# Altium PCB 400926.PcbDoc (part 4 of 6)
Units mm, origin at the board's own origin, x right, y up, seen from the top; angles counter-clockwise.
Board outline 148.5 x 63.5 mm, 4 copper layers (Top Layer, Mid-Layer 1, Mid-Layer 2, Bottom Layer), stack 1.514 mm thick; 311 components, 281 nets, 1495 pads, 2232 vias.
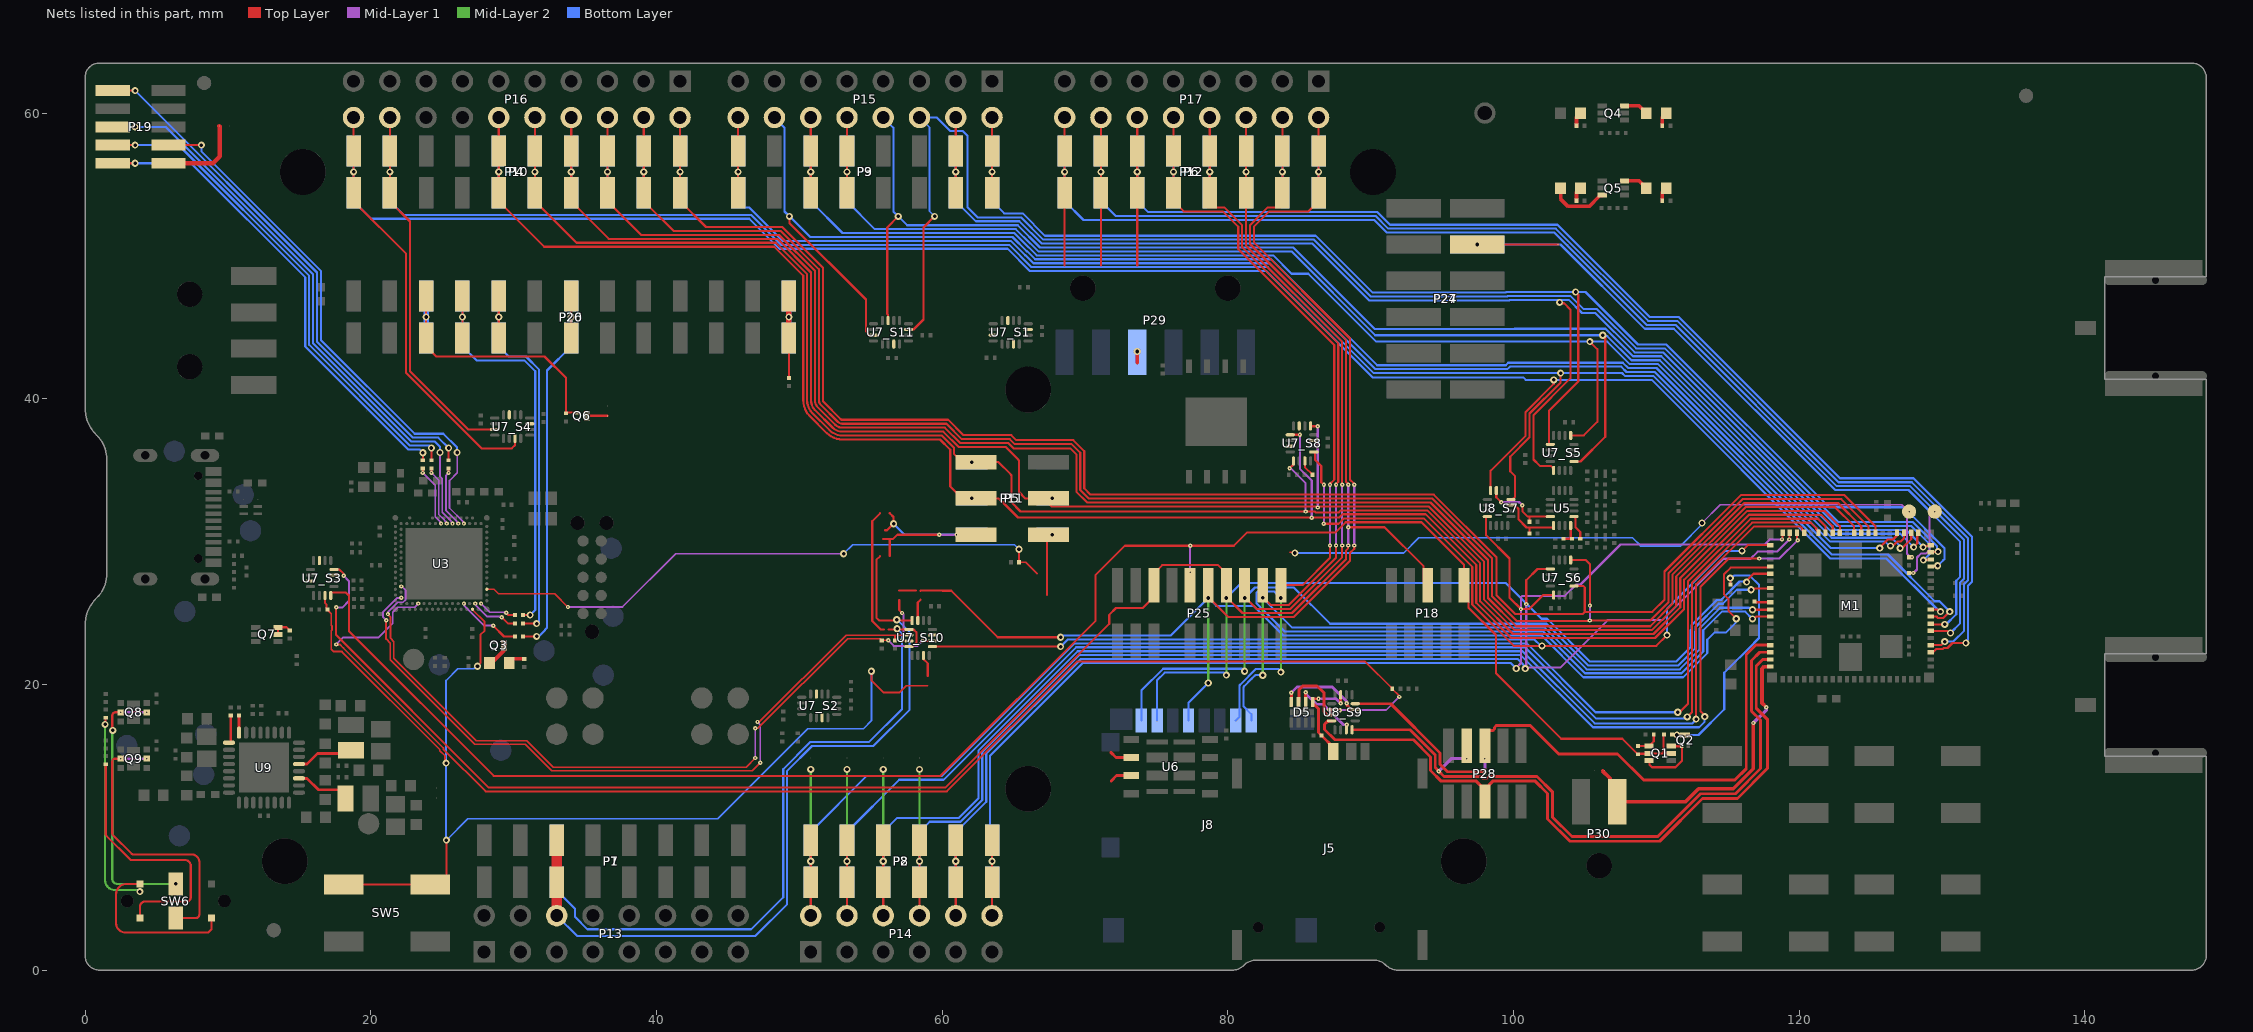
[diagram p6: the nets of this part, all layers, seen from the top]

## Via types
v1: diameter 0.5, hole 0.25, Top Layer to Bottom Layer, tented both sides, 1704 vias
v2: diameter 0.3, hole 0.1, Top Layer to Mid-Layer 1, tented top, 426 vias
v3: diameter 0.3, hole 0.1, Top Layer to Mid-Layer 1, tented both sides, 93 vias
v4: diameter 0.61, hole 0.305, Top Layer to Bottom Layer, tented both sides, 9 vias

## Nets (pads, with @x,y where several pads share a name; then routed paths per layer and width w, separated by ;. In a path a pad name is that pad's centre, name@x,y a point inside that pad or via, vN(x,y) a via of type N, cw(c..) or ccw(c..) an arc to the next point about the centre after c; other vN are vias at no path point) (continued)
NetLED1_2: LED1.2 R39.1 | length 1
  Top Layer w0.254: R39.1@104.413,59.117 104.413,59.689 LED1.2@104.698,59.974
NetLED2_1: LED2.1 Q4.3 | length 1.8
  Top Layer w0.254: Q4.3@107.75,60.499 Q4.3@107.775,60.499 108.801,60.499 109.022,60.278 109.047,60.278 109.301,60.024 LED2.1@109.301,59.999
NetLED2_2: LED2.2 R40.1 | length 1
  Top Layer w0.254: R40.1@110.413,59.117 110.413,59.689 110.698,59.974 LED2.2@110.698,59.999
NetLED3_1: LED3.1 Q5.6 | length 4.1
  Top Layer w0.254: LED3.1@103.301,54.749 103.301,53.99 103.827,53.465 105.304,53.465 Q5.6@106.039,54.201 ; Q5.6@106.202,54.201 Q5.6@106.25,54.249
NetLED3_2: LED3.2 R41.1 | length 1
  Top Layer w0.254: R41.1@104.413,53.867 104.413,54.439 104.698,54.724 LED3.2@104.698,54.749
NetLED4_1: LED4.1 Q5.3 | length 1.4
  Top Layer w0.254: Q5.3@107.75,55.249 Q5.3@107.775,55.249 108.801,55.249 LED4.1@109.022,55.028
NetLED4_2: LED4.2 R42.1 | length 1
  Top Layer w0.254: R42.1@110.413,53.867 110.413,54.439 110.698,54.724 LED4.2@110.698,54.749
NetLED5_1: LED5.1 Q3.3 | length 1.7
  Top Layer w0.25: LED5.1@28.301,21.499 28.45,21.499 29.325,22.374 Q3.3@29.325,22.724
NetLED5_2: LED5.2 R33.1 | length 1.2
  Top Layer w0.25: LED5.2@29.698,21.499 29.983,21.784 R33.1@30.75,21.784
NetM1_10: M1.10 R1.2 | length 1.1
  Top Layer w0.15: R1.2@116.885,25.799 116.935,25.749 M1.10@117.975,25.749
NetM1_99: M1.99 TP1.1 | length 5.4
  Top Layer w0.15: M1.99@127.7,27.799 v3(128,27.799)
  Mid-Layer 1 w0.15: v3(128,27.799) 128.25,28.049 128.25,28.885 128.521,29.157 128.863,29.157 129.135,29.428 129.135,31.734 v3(129.5,32.099)
NetM1_101: M1.101 SB11.2 TP2.1 | length 49.2
  Top Layer w0.125: SB11.2@84.35,29.249 84.539,29.249 84.556,29.232 84.667,29.232 v1(84.7,29.199)
  Top Layer w0.15: M1.101@127.7,28.899 127.703,28.902 127.898,28.902 v3(127.9,28.904)
  Mid-Layer 1 w0.125: v1(113.2,31.299) 114.477,32.576 127.176,32.576 127.653,32.099 v3(127.7,32.099)
  Mid-Layer 1 w0.15: v3(127.7,32.099) 127.7,32.086 127.55,31.936 127.55,29.149 127.785,28.914 127.891,28.914 v3(127.9,28.904)
  Bottom Layer w0.125: v1(84.7,29.199) 92.319,29.199 93.381,30.261 108.337,30.261 108.9,29.699 111.7,29.699 113.2,31.199 v1(113.2,31.299)
NetP5_6: P5.6 P11.6 SB18.1 SB19.2 | length 4
  Top Layer w0.152: 67.338,26.274 P5.6@67.338,30.262
  other v1: 67.722,30.48
NetP19_1: P19.1 SB15.1 SB16.1 | length 5.9
  Top Layer w0.3: P19.1@5.836,56.49 8.95,56.49 9.438,56.977 9.438,57.602 9.438,59.056 SB16.1@9.4,59.094
NetP20_3: P20.3 P26.3 Q6.1 R67.1 | length 20.9
  Top Layer w0.15: P20.3@23.876,47.752 P20.3@23.876,47.185 v1(23.876,45.72) P20.3@23.876,44.255 23.876,43.673 24.589,42.96 32.164,42.96 33.675,41.449 R67.1@33.675,39.024 ; R67.1@33.675,38.984 R67.1@33.675,39.024 ; Q6.1@34.425,39.024 R67.1@33.675,39.024
  Bottom Layer w0.381: P26.3@23.876,44.255 v1(23.876,45.72) P26.3@23.876,47.185
NetP20_13: P20.13 P26.13 R68.2 | length 9.3
  Top Layer w0.152: R68.2@49.276,41.459 P20.13@49.276,44.255 49.276,44.203 P20.13@49.71,43.769
  Top Layer w0.381: P20.13@49.276,44.255 v1(49.276,45.72) P20.13@49.276,47.185
  Bottom Layer w0.381: P26.13@49.276,44.255 v1(49.276,45.72) P26.13@49.276,47.185
NetP29_3: P29.3 SB20.2 | length 0.8
  Top Layer w0.254: 73.66,42.516 SB20.2@73.66,42.554 v1(73.66,43.309)
NetQ1_3: Q1.3 Q1.6 Q2.1 | length 4.7
  Top Layer w0.15: Q1.6@109.49,14.674 109.537,14.627 109.537,14.362 109.7,14.199 111.348,14.199 111.79,14.641 Q2.1@111.79,15.724 ; Q1.3@111.04,15.674 111.74,15.674 Q2.1@111.79,15.724 ; Q2.1@111.79,15.749 Q2.1@111.79,15.724
NetQ1_4: Q1.4 R8.2 R10.2 | length 1.7
  Top Layer w0.15: R10.2@108.715,15.684 109.5,15.684 109.825,16.009 R8.2@109.825,16.499
NetQ6_3: Q6.3 SB17.1 | length 1.5
  Top Layer w0.15: Q6.3@35.125,38.799 35.135,38.809 SB17.1@36.576,38.809
NetQ7_5: Q7.5 Q7.6 R75.2 | length 1.4
  Top Layer w0.15: Q7.5@13.5,23.499 Q7.6@13.5,23.999 14.11,23.999 R75.2@14.325,23.784
NetQ8_2: Q8.2 Q8.5 SW6.5 | length 18.6
  Top Layer w0.15: v1(1.936,16.777) 1.9,16.813 1.9,17.799 cw(c2.15,17.799) 2.15,18.049 v2(2.495,18.049)
  Mid-Layer 1 w0.15: v2(2.495,18.049) v2(4.305,18.049)
  Mid-Layer 2 w0.15: v1(1.936,16.777) 1.9,16.741 1.9,6.388 ccw(c2.254,6.388) 2.254,6.034 v1(6.35,6.034)
NetQ9_2: Q9.2 Q9.5 SW6.2 | length 20.1
  Top Layer w0.15: v2(2.495,14.799) 2.1,14.799 ccw(c2.1,14.599) 1.9,14.599 1.9,9.561 ccw(c2.05,9.561) 1.944,9.455 3.256,8.143 ccw(c3.362,8.249) 3.362,8.099 7.46,8.099 cw(c7.46,7.559) 8,7.559 8,3.899 cw(c7.735,3.899) 7.735,3.634 SW6.2@6.35,3.634
  Mid-Layer 1 w0.15: v2(2.495,14.799) v2(4.305,14.799)
NetR36_1: R36.1 U9.17 | length 2
  Top Layer w0.2: U9.17@10.075,15.924 ccw(c10.075,16.049) 10.2,16.049 R36.1@10.2,17.814
NetR37_1: R37.1 U9.16 | length 1.2
  Top Layer w0.2: R37.1@10.769,17.821 10.769,16.624 U9.16@10.775,16.624
NetR51_1: R51.1 U5.1 | length 1.7
  Top Layer w0.15: U5.1@104.235,31.749 104.34,31.644 104.34,31.013 104.68,30.673 R51.1@104.68,30.196
NetR58_1: R58.1 R59.2 U5.16 | length 1.5
  Top Layer w0.15: R59.2@103.511,30.196 R58.1@104.095,30.196 104.01,30.281 U5.16@104.01,31.124
NetR77_2: R77.2 SW6.3 SW6.4 | length 26.3
  Top Layer w0.15: v1(1.4,17.199) 1.425,17.224 1.425,17.639 R77.2@1.45,17.664 ; SW6.4@3.85,6.034 2.901,6.034 ccw(c2.901,5.308) 2.175,5.308 2.175,3.278 ccw(c2.819,3.278) 2.819,2.634 8.573,2.634 ccw(c8.573,2.784) 8.679,2.678 8.806,2.805 ccw(c8.7,2.911) 8.85,2.911 SW6.3@8.85,3.634
  Mid-Layer 2 w0.15: v1(1.4,17.199) 1.4,6.299 ccw(c2.1,6.299) 2.1,5.599 3.735,5.599 cw(c3.735,5.494) v1(3.84,5.494)
NetR79_1: R79.1 SW6.1 | length 18.8
  Top Layer w0.15: R79.1@1.45,14.414 1.45,9.511 ccw(c1.6,9.511) 1.494,9.405 3.156,7.743 ccw(c3.262,7.849) 3.262,7.699 7.011,7.699 cw(c7.011,7.31) 7.4,7.31 7.4,5.099 cw(c7.1,5.099) 7.1,4.799 4.2,4.799 ccw(c4.2,4.449) 3.85,4.449 SW6.1@3.85,3.634
NetSB13_1: SB13.1 U6.2 | length 1.6
  Top Layer w0.2: 71.812,15.249 72.177,14.884 U6.2@73.25,14.884
NetSB14_1: SB14.1 U6.3 | length 1.6
  Top Layer w0.2: SB14.1@71.838,13.249 72.203,13.614 U6.3@73.25,13.614
NO.CH1_S1: U7_S1.15
NO.CH1_S8: R35.1 U7_S8.15 | length 1.2
  Top Layer w0.125: U7_S8.15@85.4,35.649 85.4,35.208 R35.1@85.938,34.67
NO.CH1_S9: C48.1 D5.5 J5.C1 U8_S9.15 | length 6.8
  Top Layer w0.2: D5.5@85.95,18.774 85.95,18.699 86.35,18.299 86.35,16.634 C48.1@86.56,16.424 87.38,15.604 J5.C1@87.38,15.299 ; D5.5@85.95,18.999 v2(86.35,18.999) ; v2(87.9,18.674) U8_S9.15@87.9,19.274
  Mid-Layer 1 w0.2: v2(86.35,18.999) 87.575,18.999 v2(87.9,18.674)
NO.CH1_S10: SB22.2 U7_S10.15 | length 1.5
  Top Layer w0.15: U7_S10.15@58.3,24.474 58.3,25.737 58.5,25.937
NO.CH2_S1: U7_S1.3
NO.CH2_S2: U7_S2.3
NO.CH2_S3: U7_S3.3
NO.CH2_S8: U7_S8.3
NO.CH2_S9: D5.7 U8_S9.3 | length 4.9
  Top Layer w0.2: D5.7@84.95,18.774 84.975,18.799 84.975,19.624 85.25,19.899 86.255,19.899 86.725,19.429 86.725,18.11 86.986,17.849 U8_S9.3@87.275,17.849
NO.CH2_S10: SB23.2 U7_S10.3 | length 3.6
  Top Layer w0.15: SB23.2@57,25.911 SB23.2@57,25.899 57,25.199 v2(57.2,24.999) ; v2(57.15,23.049) U7_S10.3@57.675,23.049
  Mid-Layer 1 w0.15: v2(57.15,23.049) 57.3,23.199 57.3,24.899 v2(57.2,24.999)
NO.CH3_S1: U7_S1.7
NO.CH3_S3: U7_S3.7
NO.CH3_S4: U7_S4.7
NO.CH3_S8: U7_S8.7
NO.CH3_S9: D5.6 U8_S9.7 | length 4.9
  Top Layer w0.2: D5.6@85.45,18.774 v2(85.45,19.449) ; U8_S9.7@88.3,16.824 88.3,17.149 v2(88.325,17.174)
  Mid-Layer 1 w0.2: v2(85.45,19.449) 85.45,19.369 86.204,18.615 86.659,18.615 88.1,17.174 v2(88.325,17.174)
NO.CH3_S10: SB24.1 U7_S10.7 | length 1.6
  Top Layer w0.15: U7_S10.7@58.7,22.024 58.7,21.771 59,21.471 SB24.1@59,20.599 SB24.1@59,20.587
NO.CH4_S1: U7_S1.11
NO.CH4_S2: U7_S2.11
NO.CH4_S3: U7_S3.11
NO.CH4_S4: U7_S4.11
NO.CH4_S8: U7_S8.11
NO.CH4_S9: D5.8 U8_S9.11 | length 6.1
  Top Layer w0.2: D5.8@84.45,18.774 v2(84.45,19.424) ; v2(88.325,18.674) 88.325,18.549 88.625,18.249 U8_S9.11@88.925,18.249
  Mid-Layer 1 w0.2: v2(84.45,19.424) 84.85,19.824 87.315,19.824 88.325,18.814 v2(88.325,18.674)
NO.CH4_S10: U7_S10.11
NO.CH4_S11: U7_S11.11
nRESET: Q2.3 R2.1 R9.2 | length 17.6
  Top Layer w0.15: R9.2@111.1,16.499 v1@111.398,16.499 ; v1(111.44,16.458) v1@111.398,16.499 ; Q2.3@112.015,16.449 111.965,16.499 v1@111.398,16.499 ; v1(115.181,27.437) 115.191,27.428 115.191,26.993 R2.1@115.2,26.984
  Bottom Layer w0.15: v1(111.44,16.458) 112.959,16.458 114.762,18.261 114.762,20.811 116.837,22.886 116.837,22.904 117.187,23.254 117.187,26.972 116.548,27.612 115.444,27.612 115.269,27.437 v1(115.181,27.437)
P0.00: M1.56 P3.1 P9.1 P15.2 U7_S5.1 | length 99.1
  Top Layer w0.15: P3.1@63.5,54.415 v1(63.5,55.88) P3.1@63.5,57.345 P15.2@63.5,59.69 ; U7_S5.1@102.585,36.808 102.5,36.893 102.5,39.171 104.535,41.206 104.535,47.289 v1(104.35,47.474) ; M1.56@129.225,28.249 129.375,28.274 129.604,28.274 ccw(c129.603,28.424) v1(129.694,28.305)
  Bottom Layer w0.15: P9.1@63.5,57.345 v1(63.5,55.88) P9.1@63.5,54.415 63.5,53.83 64.356,52.974 65.639,52.974 67.198,51.415 86.148,51.415 90.138,47.425 99.46,47.425 99.509,47.474 v1(104.35,47.474) 105.041,47.474 108.715,43.799 110.7,43.799 122.1,32.399 127.314,32.399 130.175,29.538 130.175,28.774 130.089,28.688 129.734,28.333 cw(c129.628,28.439) v1(129.694,28.305)
P0.01: M1.57 P3.2 P9.2 P15.4 U7_S5.5 | length 103.3
  Top Layer w0.15: P3.2@60.96,54.415 v1(60.96,55.88) P3.2@60.96,57.345 P15.4@60.96,59.69 ; U7_S5.5@102.81,34.983 102.81,35.098 102.61,35.298 101.851,35.298 101.4,35.749 101.4,38.849 103.985,41.434 103.985,46.248 103.545,46.688 103.296,46.688 v1(103.235,46.749) ; v1(128.7,28.699) 128.725,28.724 129.2,28.724 M1.57@129.225,28.749
  Bottom Layer w0.15: P9.2@60.96,57.345 v1(60.96,55.88) P9.2@60.96,54.415 60.96,53.83 62.366,52.424 65.411,52.424 66.97,50.865 85.92,50.865 89.91,46.875 99.688,46.875 99.737,46.924 v1@103.235,46.924 ; v1(103.235,46.749) v1@103.235,46.924 ; v1(128.7,28.699) 129.135,29.134 129.135,29.801 127.842,31.093 122.628,31.093 110.472,43.249 108.488,43.249 105.738,45.999 104.799,45.999 103.874,46.924 v1@103.235,46.924
P0.02: M1.58 P15.6 U7_S11.15 | length 103.8
  Top Layer w0.15: U7_S11.15@57.643,44.849 58,44.849 58.695,45.544 58.695,51.991 v1(59.473,52.769) ; M1.58@129.225,29.249 129.25,29.274 129.7,29.274 v1(129.725,29.299)
  Bottom Layer w0.125: P15.6@58.42,59.69 58.518,59.592 59.117,58.992 59.117,53.125 v1(59.473,52.769)
  Bottom Layer w0.15: P15.6@58.518,59.592 58.616,59.69 59.616,59.69 60.566,58.74 61.453,58.74 61.78,58.413 61.78,53.399 62.48,52.699 65.525,52.699 67.084,51.14 86.034,51.14 90.024,47.15 99.574,47.15 99.623,47.199 103.988,47.199 104.913,46.274 105.852,46.274 108.602,43.524 110.586,43.524 122.742,31.368 127.956,31.368 129.658,29.666 129.658,29.366 v1(129.725,29.299)
P0.03: M1.59 P15.8 U7_S11.3 | length 97
  Top Layer w0.15: U7_S11.3@56.218,45.474 56.218,45.874 56.155,45.936 56.155,46.05 56.155,51.991 v1(56.933,52.769) ; v1(128.685,29.614) 128.752,29.681 129.157,29.681 M1.59@129.225,29.749
  Bottom Layer w0.15: P15.8@55.88,59.69 56.59,58.98 56.59,53.113 v1(56.933,52.769) 57.554,52.149 65.297,52.149 66.856,50.59 84.573,50.59 90.278,44.885 100.072,44.885 100.086,44.899 106.449,44.899 108.374,42.974 110.358,42.974 122.514,30.818 127.481,30.818 v1(128.685,29.614)
P0.04: M1.61 P3.5 P9.5 P15.10 U7_S5.9 | length 104.7
  Top Layer w0.15: P3.5@53.34,54.415 P3.5@53.34,57.345 P15.10@53.34,59.69 ; U7_S5.9@104.235,35.608 104.693,35.608 106.429,37.343 106.429,44.273 v1(106.252,44.449) ; v1(128.015,29.614) 128.015,29.617 128.275,29.877 128.275,30.549 M1.61@128.35,30.624
  Bottom Layer w0.15: P9.5@53.34,57.345 v1(53.34,55.88) P9.5@53.34,54.415 53.34,53.83 55.296,51.874 65.158,51.874 66.158,50.874 66.183,50.874 66.742,50.315 84.459,50.315 90.325,44.449 v1(106.252,44.449) 106.319,44.382 106.577,44.382 108.26,42.699 110.245,42.699 122.4,30.543 127.086,30.543 v1(128.015,29.614)
P0.05: M1.62 P3.6 P9.6 P15.12 U7_S5.13 | length 104.8
  Top Layer w0.15: P3.6@50.8,54.415 P3.6@50.8,57.345 P15.12@50.8,59.69 ; U7_S5.13@104.01,37.433 104.92,37.433 105.879,38.391 105.879,43.47 v1(105.35,43.999) ; v1(127.071,29.535) 127.138,29.602 127.278,29.602 127.85,30.174 M1.62@127.85,30.624
  Bottom Layer w0.15: P9.6@50.8,57.345 v1(50.8,55.88) P9.6@50.8,54.415 50.8,53.83 53.031,51.599 65.044,51.599 66.044,50.599 66.069,50.599 66.628,50.04 83.173,50.04 84.464,48.749 85.636,48.749 90.37,44.015 105.334,44.015 v1(105.35,43.999) 106.571,43.999 108.146,42.424 110.131,42.424 122.286,30.268 126.467,30.268 127.004,29.731 127.004,29.602 v1(127.071,29.535)
P0.06: M1.63 P15.14 U7_S11.7 | length 106.6
  Top Layer w0.15: v1(49.313,52.769) 49.313,52.297 54.668,46.942 54.668,44.721 54.94,44.449 U7_S11.7@55.193,44.449 ; v1(126.4,29.699) 126.519,29.699 126.572,29.752 126.606,29.752 126.862,30.007 127.108,30.007 127.35,30.249 M1.63@127.35,30.624
  Bottom Layer w0.15: P15.14@48.26,59.69 48.97,58.98 48.97,53.113 v1(49.313,52.769) 50.759,51.324 64.93,51.324 65.93,50.324 65.955,50.324 66.514,49.765 83.034,49.765 90.454,42.345 99.46,42.345 99.639,42.524 107.657,42.524 108.032,42.149 110.017,42.149 122.172,29.993 126.023,29.993 126.317,29.699 v1(126.4,29.699)
P0.07: M1.64 P3.8 P9.8 P15.16 | length 100.7
  Top Layer w0.15: P3.8@45.72,54.415 P3.8@45.72,57.345 P15.16@45.72,59.69 ; v1(125.648,29.543) 125.648,29.583 126.214,30.149 126.573,30.149 126.85,30.426 M1.64@126.85,30.624
  Bottom Layer w0.15: P9.8@45.72,57.345 v1(45.72,55.88) P9.8@45.72,54.415 45.72,53.83 46.155,53.395 46.486,53.395 48.832,51.049 64.817,51.049 65.817,50.049 65.841,50.049 66.4,49.49 82.92,49.49 90.34,42.07 99.574,42.07 99.753,42.249 107.543,42.249 107.918,41.874 109.903,41.874 122.233,29.543 v1(125.648,29.543)
P0.08: M1.67 P4.1 P10.1 P16.2 U7_S6.1 | length 121.5
  Top Layer w0.15: P16.2@41.656,59.69 P4.1@41.656,57.345 v1(41.656,55.88) P4.1@41.656,54.415 41.656,53.83 43.468,52.018 48.814,52.018 51.65,49.182 51.65,39.886 ccw(c51.8,39.886) 51.694,39.78 52.906,38.568 ccw(c53.012,38.674) 53.012,38.524 60.425,38.524 61.5,37.449 64.85,37.449 65.2,37.099 69.181,37.099 69.95,36.33 69.95,33.724 70.389,33.285 94.423,33.285 98.825,28.883 98.825,26.224 100.125,24.924 104.851,24.924 105.005,25.078 ; U7_S6.1@104.235,26.883 104.909,26.883 104.997,26.795 104.997,25.087 105.005,25.078 ; M1.67@125.35,30.624 125.35,31.074 123.175,33.249 115.92,33.249 110.575,27.904 110.575,25.929 109.724,25.078 105.005,25.078
  Bottom Layer w0.15: P10.1@41.656,54.415 v1(41.656,55.88) P10.1@41.656,57.345
P0.09: M1.68 P4.2 P10.2 P16.4 U7_S6.5 | length 126.6
  Top Layer w0.15: P16.4@39.116,59.69 P4.2@39.116,57.345 v1(39.116,55.88) P4.2@39.116,54.415 39.116,53.83 41.203,51.743 48.7,51.743 51.375,49.069 51.375,39.886 ccw(c51.8,39.886) 51.498,39.587 52.713,38.372 ccw(c53.012,38.674) 53.012,38.249 60.311,38.249 61.386,37.174 64.736,37.174 65.086,36.824 69.067,36.824 69.675,36.216 69.675,33.61 70.275,33.01 94.309,33.01 98.495,28.824 98.495,26.165 100.211,24.449 105.287,24.449 105.312,24.474 v2(105.35,24.474) 109.584,24.474 110.85,25.74 110.85,27.79 116.034,32.974 122.95,32.974 124.85,31.074 M1.68@124.85,30.624 ; U7_S6.5@104.01,28.708 105.066,28.708 105.354,28.42 v2(105.354,25.52)
  Mid-Layer 1 w0.15: v2(105.35,24.474) 105.352,24.476 105.352,25.517 v2(105.354,25.52)
  Bottom Layer w0.15: P10.2@39.116,54.415 v1(39.116,55.88) P10.2@39.116,57.345
P0.10: M1.69 P4.3 P10.3 P16.6 | length 123.3
  Top Layer w0.15: P16.6@36.576,59.69 P4.3@36.576,57.345 v1(36.576,55.88) P4.3@36.576,54.415 36.576,53.83 38.938,51.468 48.586,51.468 51.1,48.955 51.1,39.886 ccw(c51.8,39.886) 51.302,39.394 52.52,38.177 ccw(c53.012,38.674) 53.012,37.974 60.197,37.974 61.272,36.899 64.622,36.899 64.997,36.524 68.978,36.524 69.4,36.102 69.4,33.496 70.161,32.735 94.196,32.735 98.22,28.711 98.22,26.051 100.197,24.074 109.573,24.074 111.125,25.626 111.125,27.676 116.148,32.699 122.725,32.699 124.35,31.074 M1.69@124.35,30.624
  Bottom Layer w0.15: P10.3@36.576,54.415 v1(36.576,55.88) P10.3@36.576,57.345
P0.11: M1.70 P4.4 P5.4 P10.4 P11.4 P16.8 U7_S8.5 | length 131.5
  Top Layer w0.15: P16.8@34.036,59.69 P4.4@34.036,57.345 v1(34.036,55.88) P4.4@34.036,54.415 34.036,53.823 36.665,51.193 39.881,51.193 39.882,51.192 40.483,51.192 40.485,51.193 48.473,51.193 50.825,48.841 50.825,39.886 ccw(c51.8,39.886) 51.108,39.199 52.325,37.982 ccw(c53.012,38.674) 53.012,37.699 60.083,37.699 61.158,36.624 64.45,36.624 65.331,35.743 cw(c65.225,35.637) 65.375,35.637 65.375,33.536 ccw(c65.525,33.536) 65.418,33.431 ; 65.419,33.43 65.829,33.02 P5.4@67.119,33.02 ; P5.4@67.437,33.02 P5.4@67.119,33.02 ; U7_S8.5@85.8,38.099 85.825,38.074 v2(86.3,38.074) ; v2(86.3,32.385) 86.269,32.416 ccw(c86.163,32.31) 86.163,32.46 67.679,32.46 P5.4@67.119,33.02 ; v2@86.416,32.46 94.082,32.46 97.945,28.597 97.945,25.937 100.083,23.799 109.687,23.799 111.4,25.512 111.4,27.562 116.262,32.424 122.5,32.424 123.85,31.074 M1.70@123.85,30.624
  Mid-Layer 1 w0.15: v2(86.3,32.385) v2(86.3,38.074)
  Bottom Layer w0.15: P10.4@34.036,54.415 v1(34.036,55.88) P10.4@34.036,57.345
  other v1: 67.722,33.02
P0.12: M1.72 P4.5 P5.1 P10.5 P11.1 P16.10 U7_S8.13 | length 130.9
  Top Layer w0.15: P16.10@31.496,59.69 P4.5@31.496,57.345 v1(31.496,55.88) P4.5@31.496,54.415 31.496,53.83 34.408,50.918 39.767,50.918 39.769,50.917 40.597,50.917 40.599,50.918 48.359,50.918 50.55,48.727 50.55,39.886 ccw(c51.8,39.886) 50.914,39.005 52.13,37.788 ccw(c53.012,38.674) 53.012,37.424 59.969,37.424 60.844,36.549 60.844,36.12 61.404,35.56 v1(62.072,35.56) P5.1@62.357,35.56 63.944,35.56 64.803,34.702 cw(c64.697,34.596) 64.847,34.596 64.847,33.671 64.847,32.814 ccw(c64.997,32.814) 64.89,32.709 65.456,32.143 ccw(c65.562,32.249) 65.562,32.099 v2(85.45,32.099) ; v2(84.325,35.124) 84.6,35.399 U7_S8.13@84.6,35.649 ; v2@85.47,32.079 85.491,32.099 86.091,32.099 86.155,32.035 87.761,32.035 87.911,32.185 93.968,32.185 97.67,28.483 97.67,25.823 99.969,23.524 109.801,23.524 111.675,25.398 111.675,27.448 116.376,32.149 119.538,32.149 120.538,32.149 120.541,32.147 121.777,32.147 122.85,31.074 M1.72@122.85,30.624
  Mid-Layer 1 w0.15: v2(84.325,35.124) 84.411,35.124 85.45,34.085 v2(85.45,32.099)
  Bottom Layer w0.15: P10.5@31.496,54.415 v1(31.496,55.88) P10.5@31.496,57.345
P0.13/AIN0: M1.73 P4.6 P5.3 P10.6 P11.3 P16.12 U7_S8.9 | length 135.8
  Top Layer w0.15: P16.12@28.956,59.69 P4.6@28.956,57.345 v1(28.956,55.88) P4.6@28.956,54.415 28.956,53.83 32.143,50.643 39.653,50.643 39.655,50.642 40.711,50.642 40.713,50.643 48.245,50.643 50.275,48.613 50.275,39.886 ccw(c51.8,39.886) 50.72,38.81 51.936,37.594 ccw(c53.012,38.674) 53.012,37.149 59.855,37.149 60.569,36.435 60.569,33.855 61.404,33.02 P5.3@62.357,33.02 63.917,33.02 cw(c63.917,32.87) 64.023,32.976 65.281,31.718 ccw(c65.387,31.824) 65.387,31.674 v2(85.875,31.674) ; U7_S8.9@84.375,37.474 v2(85.05,37.474) ; v2@85.944,31.674 87.789,31.674 88.025,31.91 93.854,31.91 97.395,28.369 97.395,25.709 99.855,23.249 109.915,23.249 111.95,25.284 111.95,27.334 116.49,31.874 119.425,31.874 120.425,31.874 120.427,31.872 121.552,31.872 122.35,31.074 M1.73@122.35,30.624
  Mid-Layer 1 w0.15: v2(85.05,37.474) 85.05,35.099 85.875,34.274 v2(85.875,31.674)
  Bottom Layer w0.15: P10.6@28.956,54.415 v1(28.956,55.88) P10.6@28.956,57.345
  other v1: 62.072,33.02
P0.14/AIN1: M1.74 P2.1 P8.1 P14.2 SB5.1 | length 105
  Top Layer w0.15: P14.2@50.8,3.81 P2.1@50.8,6.155 v1(50.8,7.62) P2.1@50.8,9.085 ; v1(111.5,18.054) 111.567,18.121 111.692,18.121 112.225,18.654 112.225,27.22 116.604,31.599 119.311,31.599 120.311,31.599 120.313,31.597 121.327,31.597 121.85,31.074 M1.74@121.85,30.624
  Mid-Layer 2 w0.15: v1(50.8,7.62) v1(50.8,14.049)
  Bottom Layer w0.15: P8.1@50.8,6.155 v1(50.8,7.62) P8.1@50.8,9.085 50.8,9.67 54.729,13.599 59.994,13.599 69.269,22.874 100.925,22.874 105.745,18.054 v1(111.5,18.054)
P0.15/AIN2: M1.75 P2.2 P8.2 P14.4 SB6.1 | length 102
  Top Layer w0.15: P14.4@53.34,3.81 P2.2@53.34,9.085 ; v1@112.165,17.725 112.5,18.06 112.5,27.106 116.718,31.324 119.197,31.324 120.197,31.324 120.199,31.322 120.81,31.322 121.2,30.932 121.2,30.849 121.35,30.699 M1.75@121.35,30.624
  Mid-Layer 2 w0.15: v1(53.34,7.62) v1(53.34,14.049)
  Bottom Layer w0.15: P8.2@53.34,6.155 v1(53.34,7.62) P8.2@53.34,9.085 53.34,9.67 56.994,13.324 60.108,13.324 69.383,22.599 100.811,22.599 105.806,17.604 111.95,17.604 112.07,17.724 v1(112.165,17.724)
P0.16/AIN3: M1.77 P2.3 P8.3 P14.6 SB9.1 | length 100.5
  Top Layer w0.15: P14.6@55.88,3.81 P2.3@55.88,6.155 v1(55.88,7.62) P2.3@55.88,9.085 ; v1(112.792,17.568) 112.792,27.009 116.832,31.049 119.083,31.049 120.083,31.049 120.2,30.932 120.2,30.849 120.35,30.699 M1.77@120.35,30.624
  Mid-Layer 2 w0.15: v1(55.88,7.62) v1(55.88,14.049)
  Bottom Layer w0.15: P8.3@55.88,6.155 v1(55.88,7.62) P8.3@55.88,9.085 55.88,9.67 56.865,10.655 61.178,10.655 62.539,12.016 62.539,15.366 69.497,22.324 100.632,22.324 105.682,17.274 112.538,17.274 112.792,17.528 v1(112.792,17.568)
P0.17/AIN4: M1.78 P2.4 P8.4 P14.8 SB10.1 | length 97.8
  Top Layer w0.15: P14.8@58.42,3.81 P2.4@58.42,6.155 v1(58.42,7.62) P2.4@58.42,9.085 ; v1(113.39,17.747) 113.39,17.838 113.1,18.128 113.1,26.839 115.072,28.812 v3(117.2,28.812) ; M1.78@119.85,30.624 119.85,30.19 119.9,30.14 v3(119.9,30.099)
  Mid-Layer 1 w0.15: v3(117.2,28.812) 118.613,28.812 v3(119.9,30.099)
  Mid-Layer 2 w0.15: v1(58.42,7.62) v1(58.42,14.049)
  Bottom Layer w0.15: P8.4@58.42,6.155 v1(58.42,7.62) P8.4@58.42,9.085 58.42,9.67 59.13,10.38 61.292,10.38 62.814,11.902 62.814,15.252 69.611,22.049 100.518,22.049 105.568,16.999 113,16.999 113.383,17.382 113.383,17.74 v1(113.39,17.747)
P0.18/AIN5: M1.79 P2.5 P8.5 P14.10 U7_S6.9 | length 86.8
  Top Layer w0.15: P14.10@60.96,3.81 P2.5@60.96,6.155 v1(60.96,7.62) P2.5@60.96,9.085 ; v2(100.9,25.624) 100.9,27.299 101.684,28.083 U7_S6.9@102.585,28.083 ; v3(119.3,30.149) 119.325,30.174 119.325,30.599 M1.79@119.35,30.624
  Mid-Layer 1 w0.15: v1(100.828,21.102) v1@100.9,21.174 ; v2(100.9,25.624) v1@100.9,21.174 ; v3(119.3,30.149) 118.45,29.299 117.1,29.299 116.6,28.799 114.711,28.799 110.411,24.499 106.6,24.499 103.275,21.174 v1@100.9,21.174
  Bottom Layer w0.15: P8.5@60.96,6.155 v1(60.96,7.62) P8.5@60.96,9.085 60.96,9.67 61.395,10.105 61.406,10.105 63.089,11.788 63.089,15.138 69.725,21.774 100.3,21.774 100.714,21.36 100.714,21.311 100.828,21.197 v1(100.828,21.102)
P0.19/AIN6: M1.80 P2.6 P8.6 P14.12 U7_S6.13 U8_S7.12 | length 89.7
  Top Layer w0.15: P14.12@63.5,3.81 P2.6@63.5,6.155 v1(63.5,7.62) P2.6@63.5,9.085 ; U8_S7.12@98.175,31.749 98.122,31.749 98.09,31.717 98.09,30.445 99.725,28.81 99.725,26.074 v2(100.525,25.274) 101.114,25.274 102.098,26.258 U7_S6.13@102.81,26.258 ; v3(118.8,30.149) 118.825,30.174 118.825,30.599 M1.80@118.85,30.624
  Mid-Layer 1 w0.15: v1(100.2,21.111) 100.2,21.174 100.525,21.499 v2(100.525,25.274) 100.525,26.111 100.613,26.199 103.6,26.199 104.4,26.999 104.7,26.999 107.5,29.799 117.6,29.799 117.95,30.149 v3(118.8,30.149)
  Bottom Layer w0.15: P8.6@63.5,6.155 v1(63.5,7.62) P8.6@63.5,9.085 63.364,9.221 63.364,15.024 69.839,21.499 99.812,21.499 v1(100.2,21.111)
P0.20/AIN7: M1.2 U7_S8.1 U7_S10.9 | length 89
  Top Layer w0.15: U7_S10.9@59.325,22.649 v1(68.3,22.649) ; U7_S8.1@86.025,36.274 86.11,36.189 86.11,35.728 86.548,35.29 86.548,34.154 v2(86.734,33.968) ; v2(86.725,31.249) 87.761,31.249 88.136,31.624 93.728,31.624 97.12,28.232 97.12,25.596 100.017,22.699 v1(102,22.699) 110.003,22.699 v1(110.751,23.448) ; v1(116,29.349) 116.4,29.749 M1.2@117.975,29.749
  Mid-Layer 1 w0.15: v2(86.725,31.249) 86.729,31.253 86.729,33.964 v2@86.725,33.968
  Bottom Layer w0.15: v1(68.3,22.649) 68.8,23.149 101.455,23.149 101.905,22.699 v1(102,22.699) ; v1(110.751,23.448) 110.751,25.293 114.808,29.349 v1(116,29.349)
P0.21: J8.5 M1.5 P6.1 P12.1 P17.2 P25.12 SB22.1 SB23.1 | length 134.2
  Top Layer w0.15: SB23.1@57,26.587 58.168,26.587 ; 58.5,26.561 58.5,26.574 60.018,26.574 60.031,26.561 60.638,26.561 63.9,23.299 v1(68.292,23.299) ; P25.12@78.667,26.081 80.025,24.724 84.625,24.724 88.559,28.658 88.559,29.208 88.853,29.502 88.853,29.721 v2(88.859,29.727) ; P17.2@86.36,59.69 P6.1@86.36,57.345 P6.1@86.36,54.415 86.36,53.83 85.65,53.12 82.914,53.12 81.83,52.036 81.83,50.944 88.559,44.215 88.559,34.338 88.859,34.038 v2(88.859,33.968) ; v1@115.505,24.599 v1(115.6,24.599) 115.05,25.149 115.05,25.996 114.731,26.315 114.731,27.693 115.213,28.174 117.9,28.174 M1.5@117.975,28.249
  Mid-Layer 1 w0.15: v2(88.859,29.727) v2(88.859,33.968)
  Mid-Layer 2 w0.15: v1(78.635,20.099) v1(78.635,26.049)
  Bottom Layer w0.15: v1(68.292,23.299) 68.387,23.299 68.512,23.424 76.01,23.424 v1(78.635,26.049) 79.185,25.499 81.8,25.499 83.875,23.424 101.975,23.424 104.897,20.502 111.881,20.502 113.566,22.187 113.566,23.126 114.082,23.642 114.893,23.642 115.539,24.288 115.539,24.538 v1(115.6,24.599) ; J8.5@77.25,17.469 77.25,18.714 v1(78.635,20.099) ; P12.1@86.36,54.415 P12.1@86.36,57.345
  other v1: 86.36,55.88
P0.22: J8.7 M1.6 P6.2 P12.2 P17.4 P18.6 P25.6 P25.14 U7_S3.4 | length 195.1
  Top Layer w0.15: U7_S3.4@17.425,28.049 17.8,28.049 18.1,27.749 v2(18.1,27.599) ; v2(17.575,25.399) 17.575,23.462 28.263,12.774 60.228,12.774 71.7,24.246 71.7,24.869 72.178,25.346 74.042,25.346 74.825,26.129 P25.6@74.825,26.949 74.825,27.769 75.405,28.349 79.325,28.349 79.905,27.769 P25.14@79.905,26.949 79.905,26.129 81.035,24.999 84.5,24.999 88.284,28.783 88.284,29.383 88.405,29.504 88.405,29.698 v2(88.434,29.727) ; P6.2@83.675,53.395 82.8,53.395 81.555,52.15 81.555,50.83 88.284,44.102 88.284,34.188 88.434,34.038 v2(88.434,33.968) ; P6.2@83.82,54.661 v1(83.82,55.88) P6.2@83.82,57.345 P17.4@83.82,59.69 ; v2(88.425,30.999) 90.975,30.999 93.713,28.261 93.713,27.236 P18.6@94,26.949 ; v1(116.322,27.162) 116.322,27.257 116.455,27.39 116.455,27.402 116.803,27.749 M1.6@117.975,27.749
  Mid-Layer 1 w0.15: v2(17.575,25.399) 17.6,25.374 17.995,25.374 18.475,25.854 18.475,27.224 v2(18.1,27.599) ; v2(88.434,29.727) v2(88.434,33.968)
  Mid-Layer 2 w0.15: v1(79.905,20.649) v1(79.905,26.049)
  Bottom Layer w0.15: J8.7@75.05,17.469 75.05,20.288 75.586,20.824 79.73,20.824 v1(79.905,20.649) ; v1(79.905,26.049) 80.955,27.099 99.463,27.099 101.963,24.599 102.356,24.599 105.353,21.602 111.403,21.602 112.4,22.599 112.4,23.773 112.466,23.839 112.466,24.131 114.252,25.918 114.545,25.918 115.827,27.2 116.285,27.2 v1(116.322,27.162) ; P12.2@83.82,54.415 P12.2@83.82,57.345
P0.23: J8.8 M1.8 P6.3 P12.3 P17.6 P25.16 | length 103.7
  Top Layer w0.15: P25.16@81.175,26.949 81.175,26.124 81.18,26.124 82.03,25.274 84.375,25.274 88.009,28.908 v2(88.009,29.727) ; P17.6@81.28,59.69 P6.3@81.28,57.345 v1(81.28,55.88) P6.3@81.28,54.415 81.28,50.716 88.009,43.988 v2(88.009,33.968) ; v1(116.643,26.626) 116.71,26.693 116.875,26.693 116.906,26.724 117.95,26.724 M1.8@117.975,26.749
  Mid-Layer 1 w0.15: v2(88.009,29.727) v2(88.009,33.968)
  Mid-Layer 2 w0.15: v1(81.175,20.922) ccw(c81.025,20.93) 81.175,20.93 v1(81.175,26.049)
  Bottom Layer w0.15: J8.8@73.95,17.469 73.95,19.577 75.472,21.099 81,21.099 81.161,20.938 cw(c81.054,20.832) v1(81.175,20.922) ; v1(81.175,26.049) 81.909,26.783 84.63,26.783 87.164,24.249 102.317,24.249 105.239,21.327 111.528,21.327 112.7,22.499 112.7,23.684 112.741,23.725 112.741,24.017 114.366,25.643 114.659,25.643 115.642,26.626 v1(116.643,26.626) ; P12.3@81.28,54.415 P12.3@81.28,57.345
P0.24: J8.1 M1.11 P6.4 P12.4 P17.8 P25.18 | length 94.9
  Top Layer w0.15: P6.4@78.6,53.395 79.76,53.395 81.005,52.15 81.005,50.602 87.734,43.874 87.734,34.188 87.584,34.038 v2(87.584,33.968) ; P6.4@78.74,54.415 P17.8@78.74,59.69 ; P25.18@82.445,26.949 82.445,26.129 P25.18@82.485,26.089 ; v1(82.454,26.058) P25.18@82.485,26.089 ; v2(87.584,29.727) 87.584,28.883 84.25,25.549 83.025,25.549 P25.18@82.485,26.089 ; v1(116.737,25.225) 116.741,25.228 117.954,25.228 M1.11@117.975,25.249
  Mid-Layer 1 w0.15: v2(87.584,29.727) v2(87.584,33.968)
  Mid-Layer 2 w0.15: v1(82.445,20.636) 82.445,26.049 v1(82.454,26.058)
  Bottom Layer w0.15: P12.4@78.74,54.415 P12.4@78.74,57.345 ; J8.1@81.65,17.469 81.65,17.909 81.1,18.459 81.1,19.762 cw(c81.25,19.762) 81.143,19.867 81.653,20.377 cw(c81.759,20.27) 81.658,20.382 ccw(c81.175,20.922) 81.715,20.438 cw(c81.826,20.338) 81.72,20.443 81.882,20.605 cw(c81.987,20.499) 81.987,20.649 82.386,20.649 cw(c82.385,20.499) v1(82.445,20.636) ; v1(82.454,26.058) 82.454,26.04 84.52,23.974 102.203,23.974 105.125,21.052 111.653,21.052 113.016,22.415 113.016,23.904 114.48,25.368 116.5,25.368 116.643,25.225 v1(116.737,25.225)
  other v1: 78.74,55.88
P0.25: J8.2 M1.12 P6.5 P12.5 P17.10 P25.20 | length 99.9
  Top Layer w0.15: P6.5@76.2,54.415 76.2,53.83 76.91,53.12 79.646,53.12 80.73,52.036 80.73,50.488 87.459,43.76 87.459,34.338 87.159,34.038 v2(87.159,33.968) ; P6.5@76.2,54.712 v1(76.2,55.88) P6.5@76.2,57.345 P17.10@76.2,59.69 ; v1(83.715,26.049) P25.20@83.715,26.949 85.25,26.949 87.159,28.858 v2(87.159,29.727) ; v1(116.737,24.583) 116.83,24.583 116.996,24.749 M1.12@117.975,24.749
  Mid-Layer 1 w0.15: v2(87.159,29.727) v2(87.159,33.968)
  Mid-Layer 2 w0.15: v1(83.715,20.861) v1(83.715,26.049)
  Bottom Layer w0.15: P12.5@76.2,54.415 P12.5@76.2,57.345 ; J8.2@80.55,17.469 80.825,17.744 80.825,19.875 cw(c80.975,19.875) 80.868,19.981 81.465,20.577 cw(c81.57,20.471) 81.47,20.582 ; 81.47,20.583 ccw(c81.175,20.922) 81.513,20.626 cw(c81.626,20.527) 81.519,20.632 81.93,21.043 cw(c82.036,20.936) 82.036,21.086 83.518,21.086 83.568,21.036 83.677,21.036 cw(c83.565,20.936) 83.715,20.936 v1(83.715,20.861) ; v1(83.715,26.049) 83.256,26.508 82.109,26.508 82.004,26.403 82.004,25.695 84,23.699 102.089,23.699 105.011,20.777 111.767,20.777 113.291,22.301 113.291,23.79 114.594,25.093 116.227,25.093 v1(116.737,24.583)
P0.26: M1.44 P6.6 P12.6 P17.12 SB3.1 | length 92.4
  Top Layer w0.15: SB3.1@73.66,49.337 SB3.1@73.66,49.349 P6.6@73.66,54.415 P6.6@73.66,57.345 P17.12@73.66,59.69 ; M1.44@129.225,22.249 129.383,22.249 129.608,22.474 130.051,22.474 130.126,22.549 130.386,22.549 130.736,22.899 v1(131.675,22.899)
  Bottom Layer w0.15: P12.6@73.66,57.345 v1(73.66,55.88) P12.6@73.66,54.415 73.66,53.83 74.424,53.066 90.479,53.066 91.36,52.185 103.079,52.185 109.54,45.724 111.575,45.724 122.867,34.432 128.003,34.432 132.1,30.336 132.1,27.188 131.825,26.913 131.825,23.144 131.675,22.994 v1(131.675,22.899)
P0.27: M1.45 P6.7 P12.7 P17.14 SB4.1 | length 93.7
  Top Layer w0.15: SB4.1@71.12,49.337 P6.7@71.12,54.415 P6.7@71.12,57.345 P17.14@71.12,59.69 ; M1.45@129.225,22.749 129.937,22.749 130.187,22.999 v1(130.2,22.999)
  Bottom Layer w0.15: P12.7@71.12,57.345 v1(71.12,55.88) P12.7@71.12,54.415 71.12,53.83 72.159,52.791 90.365,52.791 91.246,51.91 102.965,51.91 109.426,45.449 111.461,45.449 122.753,34.157 127.889,34.157 131.825,30.222 131.825,27.301 131.55,27.026 131.55,23.749 130.8,22.999 v1(130.2,22.999)
P0.28: M1.47 P6.8 P12.8 P17.16 SB7.1 | length 95
  Top Layer w0.15: SB7.1@68.58,49.337 SB7.1@68.58,49.349 P6.8@68.58,54.415 P6.8@68.58,57.345 P17.16@68.58,59.69 ; M1.47@129.225,23.749 130.355,23.749 130.505,23.599 v1(130.6,23.599)
  Bottom Layer w0.15: P12.8@68.58,57.345 v1(68.58,55.88) P12.8@68.58,54.415 68.58,53.83 69.894,52.516 90.251,52.516 91.132,51.635 102.851,51.635 109.312,45.174 111.347,45.174 122.639,33.882 127.775,33.882 131.55,30.108 131.55,27.415 131.275,27.14 131.275,24.274 v1(130.6,23.599)
P0.29: M1.48 P24.4 P27.4 SB8.1 | length 55.4
  Top Layer w0.15: v1(97.472,50.8) SB8.1@103.122,50.8 SB8.1@103.135,50.8 ; M1.48@129.225,24.249 129.275,24.199 v1(130.2,24.199)
  Bottom Layer w0.15: v1(97.472,50.8) 103.297,50.8 109.198,44.899 111.233,44.899 122.525,33.607 127.661,33.607 131.275,29.994 131.275,27.529 131,27.254 131,24.913 130.286,24.199 v1(130.2,24.199)
P0.30: M1.49 P4.9 P10.9 P16.18 U7_S4.15 U8_S7.4 | length 162.2
  Top Layer w0.15: P4.9@21.336,53.823 22.75,52.409 22.75,41.913 26.814,37.849 U7_S4.15@28.675,37.849 ; P4.9@21.336,54.415 v1(21.336,55.88) P4.9@21.336,57.345 P16.18@21.336,59.69 ; U8_S7.4@99.825,32.949 99.93,32.949 100.118,33.136 100.118,34.581 99.775,34.924 99.775,35.949 101.125,37.299 101.125,38.963 103.3,41.138 v1(103.3,41.799) ; M1.49@129.225,24.749 129.614,24.749 129.714,24.649 130.086,24.649 130.536,25.099 v1(130.55,25.099)
  Bottom Layer w0.15: P10.9@21.336,57.345 v1(21.336,55.88) P10.9@21.336,54.415 21.336,53.83 22.292,52.874 46.618,52.874 48.718,50.774 64.703,50.774 66.262,49.215 82.806,49.215 90.226,41.795 103.3,41.795 103.304,41.799 107.604,41.799 107.804,41.599 109.789,41.599 122.294,29.093 126.222,29.093 129.495,25.821 129.828,25.821 v1(130.55,25.099)
P0.31: M1.50 P4.10 P10.10 P16.20 U7_S4.3 U8_S7.8 | length 166
  Top Layer w0.15: P4.10@18.796,53.83 22.475,50.151 22.475,41.799 27.75,36.524 29.875,36.524 30.1,36.749 U7_S4.3@30.1,37.224 ; P4.10@18.796,54.415 v1(18.796,55.88) P4.10@18.796,57.345 P16.20@18.796,59.69 ; U8_S7.8@98.4,33.574 98.4,34.963 100.85,37.413 100.85,39.077 102.825,41.052 v1(102.825,41.324) ; M1.50@129.225,25.249 129.655,25.249 129.805,25.099 v1(129.9,25.099)
  Bottom Layer w0.15: P10.10@18.796,57.345 v1(18.796,55.88) P10.10@18.796,54.415 18.796,53.83 20.027,52.599 46.504,52.599 48.604,50.499 64.589,50.499 66.148,48.94 82.692,48.94 90.133,41.499 100.686,41.499 100.861,41.324 v1(102.825,41.324) 109.675,41.324 122.181,28.818 126.108,28.818 129.828,25.099 v1(129.9,25.099)
RESET: P18.10 P25.10 Q1.2 Q1.5 R9.1 R10.1 U7_S3.16 | length 123.1
  Top Layer w0.15: U7_S3.16@17.2,26.224 17.2,26.392 17.232,26.424 18.27,26.424 18.475,26.219 18.475,23.728 28.604,13.599 59.886,13.599 70.75,24.463 70.75,27.666 72.793,29.709 v2(77.365,29.709) 80.418,29.709 81.336,30.627 87.528,30.627 88.25,31.349 93.565,31.349 96.54,28.374 P18.10@96.54,26.949 96.845,26.644 96.845,25.385 98.775,23.455 98.775,20.775 103.351,16.199 107.615,16.199 108.7,15.114 R10.1@108.715,15.114 108.745,15.144 109.46,15.144 Q1.5@109.49,15.174 ; Q1.5@109.49,15.199 109.55,15.199 109.575,15.174 110.515,15.174 ; R9.1@110.53,16.499 110.515,16.484 110.515,15.416 110.515,15.199 111.015,15.199 Q1.2@111.04,15.174
  Mid-Layer 1 w0.15: v2(77.365,27.849) v2(77.365,29.709)
RESET_BOTTOM: P7.3 SB25.1 SB27.1 U7_S10.1 U7_S10.4 | length 58.8
  Top Layer w0.15: SB25.1@55.662,31.98 55.112,31.43 55.112,24.436 55.7,23.849 55.929,23.849 ; 56.264,23.849 U7_S10.1@57.675,23.849 58,23.849 58.2,23.649 58.2,22.921 57.928,22.649 U7_S10.4@57.675,22.649
  Bottom Layer w0.15: P7.3@33.02,6.155 33.02,5.57 34.311,4.279 34.311,3.716 35.166,2.86 46.632,2.86 48.875,5.103 48.875,14.061 50.788,15.974 54.892,15.974 57.2,18.282 57.2,23.549 v1(56.85,23.899)
  Bottom Layer w0.381: P7.3@33.02,6.155 P7.3@33.02,9.085
RESET_BUTTON: R23.1 SB21.2 SB24.2 SW5.2 U3.AL27 U7_S3.15 | length 85.7
  Top Layer w0.125: U7_S3.15@16.8,26.224 16.8,25.695 16.908,25.586 16.908,25.301 R23.1@16.96,25.249 16.96,25.234 17.237,24.956 17.237,24.139 17.29,24.086 17.29,23.806 17.237,23.754 17.237,22.461 17.4,22.299 17.982,22.299 24.837,15.444 24.837,15.361 25.2,14.999 25.2,14.566 v1(25.27,14.495) ; SW5.2@18.111,5.999 24.662,5.999 25.3,6.636 v1(25.3,9.099) ; U3.AL27@27.125,25.234 27.967,24.392 27.967,23.766 27.675,23.474 27.675,21.474 v1(27.475,21.274) ; v1(55.05,20.924) 55.05,20.284 55.91,19.424 57.013,19.424 57.5,19.911 SB24.2@59,19.911
  Bottom Layer w0.125: v1@25.27,14.495 25.27,20.269 26.1,21.099 27.2,21.099 27.375,21.274 v1(27.475,21.274) ; v1(25.27,14.495) 25.27,9.128 v1(25.3,9.099) 26.8,10.599 44.3,10.599 50.6,16.899 54.5,16.899 55.05,17.449 v1(55.05,20.924)
RESET_IN_CTRL: R73.2 U3.AD2 U7_S10.10 | length 52.2
  Top Layer w0.125: v2(21.2,24.924) 21.2,24.877 21.387,24.689 21.387,23.957 21.387,23.225 21.616,22.997 21.616,21.842 27.397,16.061 30.91,16.061 32.772,14.199 46.275,14.199 v2(46.925,14.849) ; v2(46.925,16.924) 47.106,16.924 53.381,23.199 55.66,23.199 R73.2@55.775,23.084 v2(56.225,23.084)
  Top Layer w0.15: v2(58.625,23.049) U7_S10.10@59.325,23.049
  Mid-Layer 1 w0.125: v2(21.2,24.924) 21.2,25.061 21.885,25.745 22.259,25.745 22.437,25.924 22.437,26.587 22.167,26.858 v2(22.125,26.858) ; v2(46.925,14.849) v2(46.925,16.924)
  Mid-Layer 1 w0.15: v2(56.225,23.084) 56.61,22.699 58.275,22.699 v2(58.625,23.049)
RESET_OUT_CTRL: R72.1 U3.AH2 U7_S10.2 | length 51
  Top Layer w0.125: v2(21.075,24.499) 21.075,23.184 21.366,22.893 21.366,21.739 27.293,15.811 30.806,15.811 32.669,13.949 46.7,13.949 v2(47.275,14.524) ; v2(47.075,17.374) 47.202,17.374 53.277,23.449 56.681,23.449 ; R72.1@56.7,23.084 56.7,23.431 56.681,23.449 ; U7_S10.2@57.675,23.449 56.681,23.449
  Mid-Layer 1 w0.125: v2(21.075,24.499) 20.862,24.712 20.862,25.077 21.844,26.058 v2(22.125,26.058) ; v2(47.075,17.374) 47.262,17.186 47.262,14.536 v2(47.275,14.524)
RESET_P5_BOTTOM: P11.5 SB25.2 SB26.2 | length 7.4
  Top Layer w0.15: 56,30.792 56.143,30.792 v1(56.6,31.249) 56.6,31.718 SB25.2@56.338,31.98
  Bottom Layer w0.15: v1(56.6,31.249) 57.369,30.48 P11.5@62.072,30.48
RESET_P5_TOP: P5.5 SB26.1 SB28.2 | length 8.1
  Top Layer w0.15: 55.853,30.168 56.353,30.168 ; SB28.2@56.338,28.98 56.338,30.152 56.353,30.168 ; v2(59.794,30.48) 56.869,30.48 56.557,30.168 56.353,30.168 ; v2(61.006,30.48) P5.5@62.357,30.48 P5.5@62.674,30.48
  Mid-Layer 1 w0.15: v2(59.794,30.48) v2(61.006,30.48)
RESET_TOP: P1.3 P13.6 SB27.2 SB28.1 U7_S10.16 | length 56.3
  Top Layer w0.15: SB28.1@55.662,28.98 55.4,28.718 55.4,24.669 55.595,24.474 56,24.474 U7_S10.16@57.9,24.474
  Top Layer w0.75: P13.6@33.02,3.81 P1.3@33.02,6.155 P1.3@33.02,9.085
  Bottom Layer w0.15: P13.6@33.02,3.81 34.436,2.394 46.934,2.394 49.15,4.61 49.15,13.947 50.889,15.686 55.187,15.686 57.725,18.224 57.725,23.66 56.861,24.524 v1(56.825,24.524)
SCL_EXT: R49.1 U5.12 U8_S7.7 | length 5.4
  Top Layer w0.15: U8_S7.7@98.8,33.574 98.8,33.099 v2(99.15,32.749) ; v2(100.625,32.549) 100.625,32.122 100.998,31.749 U5.12@102.585,31.749 ; R49.1@101.118,31.384 101.118,31.746
  Mid-Layer 1 w0.15: v2(99.15,32.749) 100.425,32.749 v2(100.625,32.549)
SDA_EXT: R48.1 U5.13 U8_S7.3 | length 4.5
  Top Layer w0.15: U8_S7.3@99.825,32.549 100.078,32.549 100.35,32.277 100.35,31.556 100.917,30.989 101.124,30.989 ; R48.1@101.118,30.571 101.118,30.983 101.124,30.989 ; U5.13@102.81,31.017 102.781,30.989 101.124,30.989
SHIELD_DETECT: R69.1 SB18.2 U3.AE31 | length 42.2
  Top Layer w0.125: U3.AE31@28.125,26.658 28.631,26.658 28.94,26.349 32.875,26.349 v2(33.804,25.42) ; v1(65.385,29.464) R69.1@65.385,28.549 65.862,28.549 SB18.2@66.662,27.749
  Mid-Layer 1 w0.125: v2(33.804,25.42) 37.621,25.42 41.35,29.149 v1(53.1,29.149)
  Bottom Layer w0.125: v1(53.1,29.149) 53.733,29.782 65.066,29.782 v1(65.385,29.464)
SIM_1V8: M1.19 P30.2 SB12.1 | length 20.5
  Top Layer w0.25: P30.2@107.27,11.799 112.058,11.799 112.958,12.699 115.397,12.699 116.8,14.102 v3(116.8,17.299) ; v3(117.7,18.399) 117.4,18.699 117.4,21.103 117.546,21.249 M1.19@117.975,21.249
  Top Layer w0.254: 106.24,13.944 106.762,13.421 P30.2@106.762,12.307
  Mid-Layer 1 w0.25: v3(116.8,17.299) 117.69,18.189 117.69,18.389 v3(117.7,18.399)
SIM_CLK: M1.18 P28.5 U8_S9.4 | length 49
  Top Layer w0.203: U8_S9.4@87.275,17.449 87.252,17.426 86.994,17.426 86.773,17.205 86.773,16.851 87.498,16.126 92.998,16.126 94.197,14.927 94.197,13.969 94.941,13.226 97.398,13.226 P28.5@98,12.624 ; P28.5@98,11.799 P28.5@98,12.624 ; M1.18@117.975,21.749 117.45,21.749 117,21.299 117,18.327 117.8,17.527 117.8,14.14 115.679,12.019 113.24,12.019 110.238,9.018 103.953,9.018 102.394,10.577 102.394,12.355 101.523,13.226 98.552,13.226 98,12.674 P28.5@98,12.624
SIM_IO: M1.17 P28.4 U8_S9.8 | length 47
  Top Layer w0.203: U8_S9.8@88.7,16.824 92.764,16.824 94.525,15.063 94.525,14.174 v2(94.775,13.924) 95.145,13.554 97.738,13.554 97.844,13.447 98.156,13.447 98.262,13.554 101.659,13.554 102.722,12.491 102.722,10.713 104.089,9.346 110.102,9.346 113.104,12.347 115.543,12.347 117.3,14.105 117.3,17.499 116.672,18.127 116.672,21.671 117.25,22.249 M1.17@117.975,22.249
  Mid-Layer 1 w0.203: v2(94.775,13.924) 95.65,14.799 v2(96.73,14.799)
SIM_RST: M1.16 P28.6 U8_S9.12 | length 43.8
  Top Layer w0.203: U8_S9.12@88.925,18.649 91.403,18.649 94.853,15.199 94.853,14.405 95.377,13.882 97.874,13.882 97.883,13.872 97.925,13.872 97.974,13.824 v2(98,13.824) ; P28.6@98,15.699 98,16.481 98.278,16.759 98.544,16.759 98.663,16.878 98.663,16.993 98.796,17.126 101.18,17.126 103.168,15.137 107.285,15.137 109.125,13.297 115.498,13.297 116.3,14.099 116.3,22.099 116.974,22.773 117.952,22.773 M1.16@117.975,22.749
  Mid-Layer 1 w0.203: v2(98,13.824) v2(98,14.799)
SIM_SELECT: R63.1 U3.AK8 U8_S9.2 | length 96.1
  Top Layer w0.125: v2(17.575,22.799) 17.836,22.799 18.086,22.549 25.087,15.548 25.087,15.465 28.041,12.511 60.337,12.511 69.426,21.6 89.628,21.6 91.552,19.676 91.552,19.646 91.967,19.232 91.967,19.157 v2(92,19.124) ; U8_S9.2@87.275,18.249 87.8,18.249 v2(87.85,18.199)
  Mid-Layer 1 w0.125: v2(17.575,22.799) 18.063,23.287 20.557,23.287 21.537,24.268 21.537,25.045 21.892,25.399 23.066,25.399 v2(23.325,25.658) ; v2(87.85,18.199) 91.075,18.199 v2(92,19.124)
SW1: L7.2 U9.3 | length 3.9
  Top Layer w0.2: U9.3@14.975,13.424 15.538,13.424 16.341,12.621 17.762,12.621 18.227,12.156 L7.2@18.227,11.996
SW2: L8.2 U9.5 | length 4
  Top Layer w0.2: U9.5@14.975,14.424 15.538,14.424 16.28,15.166 18.402,15.166 L8.2@18.625,15.389
SWD0.RESET: P19.10 R30.2 | length 37.6
  Top Layer w0.125: R30.2@25.45,35.693 v1(25.45,36.549)
  Top Layer w0.15: P19.10@1.936,61.57 v1(3.505,61.57)
  Bottom Layer w0.15: v1(3.505,61.57) 16.235,48.839 16.235,44 22.961,37.274 24.725,37.274 v1(25.45,36.549)
SWD0.SWDCLK: P19.4 R29.2 | length 34.8
  Top Layer w0.125: R29.2@24.25,35.693 v1(24.25,36.549)
  Top Layer w0.15: P19.4@1.936,57.76 v1(3.505,57.76)
  Bottom Layer w0.15: v1(3.505,57.76) 6.537,57.76 15.685,48.612 15.685,43.772 22.733,36.724 24.075,36.724 v1(24.25,36.549)
SWD0.SWDIO: P19.2 R28.2 | length 33.5
  Top Layer w0.125: R28.2@23.65,35.693 v1(23.65,36.218)
  Top Layer w0.15: P19.2@1.936,56.49 v1(3.505,56.49)
  Bottom Layer w0.15: v1(3.505,56.49) 7.418,56.49 15.41,48.498 15.41,43.658 22.619,36.449 23.419,36.449 v1(23.65,36.218)
SWD0_CLK: R29.1 U3.B18 | length 4.3
  Top Layer w0.125: v2(24.25,34.808) R29.1@24.25,35.123
  Mid-Layer 1 w0.125: v2(24.25,34.808) 24.762,34.296 24.762,31.896 25.062,31.595 25.065,31.595 25.262,31.398 25.262,31.395 25.325,31.333 v2(25.325,31.258)
SWD0_IO: R28.1 U3.B16 | length 4.4
  Top Layer w0.125: v2(23.65,34.808) R28.1@23.65,35.123
  Mid-Layer 1 w0.125: v2(23.65,34.808) 24.512,33.946 24.512,31.748 24.862,31.398 24.862,31.32 v2(24.925,31.258)
SWD0_RESET: R30.1 U3.B22 | length 4.3
  Top Layer w0.125: v2(25.45,34.808) R30.1@25.45,35.123
  Mid-Layer 1 w0.125: v2(25.45,34.808) 25.262,34.62 25.262,32.198 26.062,31.398 26.062,31.345 26.125,31.283 v2(26.125,31.258)
SWD0_SEL: P19.3 U3.B24 | length 38
  Top Layer w0.15: P19.3@5.836,57.76 v1(8.139,57.76)
  Mid-Layer 1 w0.125: v1(26.05,36.233) 26.05,34.808 25.512,34.27 25.512,32.348 26.462,31.398 26.462,31.32 v2(26.525,31.258)
  Bottom Layer w0.15: v1(8.139,57.76) 8.139,57.324 16.51,48.953 16.51,44.114 23.075,37.549 25.086,37.549 26.05,36.585 v1(26.05,36.233)
SWD0_SWO: P19.6 U3.B20 | length 40.8
  Top Layer w0.15: P19.6@1.936,59.03 v1(3.505,59.03)
  Mid-Layer 1 w0.125: v1(24.85,36.233) 24.85,34.562 25.012,34.399 25.012,32.048 25.662,31.398 25.662,31.345 25.725,31.283 v2(25.725,31.258)
  Bottom Layer w0.15: v1(3.505,59.03) 5.656,59.03 15.96,48.725 15.96,43.886 22.847,36.999 24.5,36.999 24.85,36.649 v1(24.85,36.233)
SWD1.RESET: P20.7 P26.7 R27.2 | length 28.8
  Top Layer w0.15: R27.2@30.66,23.358 v1(31.609,23.358) ; P20.7@34.036,44.255 v1(34.036,45.72) P20.7@34.036,47.185
  Bottom Layer w0.15: v1(31.609,23.358) 31.759,23.358 32.2,23.799 32.2,23.824 32.337,23.961 32.337,41.971 34.036,43.67 P26.7@34.036,44.255 v1(34.036,45.72) P26.7@34.036,47.185
SWD1.SWDCLK: P20.5 P26.5 R26.2 | length 29.3
  Top Layer w0.15: P20.5@28.956,43.688 P20.5@28.956,44.255 P20.5@28.956,47.185 ; R26.2@30.66,24.258 v1(31.609,24.258)
  Bottom Layer w0.15: P26.5@28.956,47.185 v1(28.956,45.72) 28.956,43.67 29.666,42.96 30.864,42.96 31.787,42.036 31.787,24.436 v1(31.609,24.258)
SWD1.SWDIO: P20.4 P26.4 R25.2 | length 29.9
  Top Layer w0.15: P20.4@26.416,44.348 P20.4@26.416,47.185 ; R25.2@30.66,24.858 v1(31.159,24.858)
  Bottom Layer w0.15: P26.4@26.416,47.185 v1(26.416,45.72) P26.4@26.416,44.255 26.416,43.67 27.401,42.685 30.75,42.685 31.512,41.923 31.512,25.211 v1(31.159,24.858)
SWD1_CLK: R26.1 U3.AK28 | length 3.4
  Top Layer w0.15: v2(29.176,24.709) 29.627,24.258 R26.1@30.09,24.258
  Mid-Layer 1 w0.125: v2(27.325,25.658) 27.325,25.611 27.387,25.548 27.387,25.518 28.16,24.746 29.015,24.746 29.019,24.743 29.143,24.743 v2(29.176,24.709)
SWD1_IO: R25.1 U3.AK30 | length 2.7
  Top Layer w0.15: v2(29.477,25.01) 29.628,24.858 R25.1@30.09,24.858
  Mid-Layer 1 w0.125: v2(27.725,25.658) 28.336,25.047 29.316,25.047 29.319,25.043 29.443,25.043 v2(29.477,25.01)
SWD1_RESET: R27.1 U3.AK24 | length 4.6
  Top Layer w0.15: v2(28.575,24.108) 29.325,23.358 R27.1@30.09,23.358
  Mid-Layer 1 w0.125: v2(26.525,25.658) 26.558,25.625 26.558,25.496 27.937,24.117 28.566,24.117 v2(28.575,24.108)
